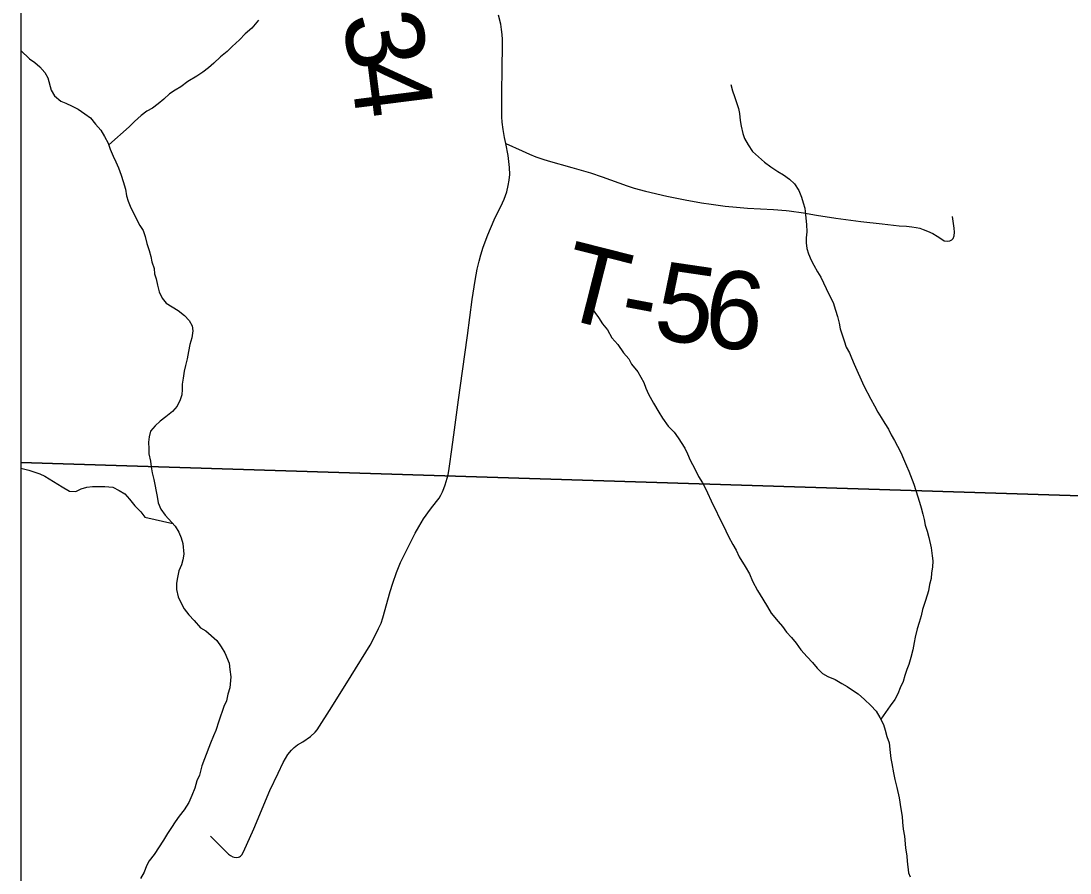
# Model space of a CAD drawing. Extents: x -3.3 to 34, y 0 to 56.8.
# Drawn here: x -3.304 to -2.54, y 30.466 to 31.087 of the extents above; entities that cross this region are included whole.
import ezdxf

# ---------------------------------------------------------------- set-up
doc = ezdxf.new("R2010")
doc.units = 0
for name, color, linetype in [('GM_X_Corporation', 7, 'Continuous'), ('GM_X_Township_Road', 7, 'Continuous'), ('GM_X_Township_Road_Text', 7, 'Continuous'), ('GT_Project_Soil_Layers', 7, 'Continuous'), ('SH_Data', 7, 'Continuous')]:
    doc.layers.add(name, color=color, linetype=linetype)

msp = doc.modelspace()

# ---------------------------------------------------------------- linework, layer by layer
at = {"layer": 'GM_X_Corporation'}
msp.add_lwpolyline([(-3.30393, 33.7379), (-3.30393, 28.07705), (1.56989, 28.07705), (1.59424, 28.73823), (1.64589, 29.81689), (1.65379, 30.0279), (1.68495, 30.79802), (1.68821, 30.98908), (1.68831, 30.9953), (1.68852, 31.00753), (1.69805, 31.56614), (1.74587, 32.36303)], dxfattribs=at)
for points in [[(-3.30393, 31.76721), (-3.30393, 30.76526), (-2.39277, 30.73672), (-2.35994, 31.74572)], [(-3.30393, 30.76526), (-3.30393, 29.75009), (-2.4143, 29.73246), (-2.39277, 30.73672)]]:
    msp.add_lwpolyline(points, close=True, dxfattribs=at)
at = {"layer": 'GM_X_Township_Road'}
for points in [[(-2.95067, 30.99779), (-2.95158, 31.00215), (-2.95268, 31.00803), (-2.95328, 31.01331), (-2.95355, 31.01711), (-2.95364, 31.03428), (-2.95329, 31.05262), (-2.95298, 31.06898), (-2.95306, 31.07358), (-2.95331, 31.0772), (-2.95372, 31.08082), (-2.95438, 31.08468), (-2.95595, 31.09131)], [(-3.16579, 30.49312), (-3.15398, 30.4811), (-3.1527, 30.47987), (-3.15124, 30.47886), (-3.14965, 30.47807), (-3.14851, 30.47774), (-3.14708, 30.47756), (-3.14545, 30.47785), (-3.1448, 30.47807), (-3.14398, 30.47849), (-3.14353, 30.479), (-3.14309, 30.47955), (-3.14179, 30.48165), (-3.13416, 30.49834), (-3.12262, 30.52641), (-3.11664, 30.53902), (-3.11294, 30.54667), (-3.10941, 30.55251), (-3.10694, 30.55579), (-3.10497, 30.55768), (-3.10242, 30.55949), (-3.09856, 30.56188), (-3.09289, 30.56574), (-3.08968, 30.56878), (-3.08812, 30.57051), (-3.07738, 30.58736), (-3.06339, 30.60989), (-3.04948, 30.63231), (-3.04628, 30.63824), (-3.0434, 30.64425), (-3.04159, 30.64827), (-3.04027, 30.65205), (-3.03493, 30.67132), (-3.03304, 30.67737), (-3.03041, 30.68509), (-3.02729, 30.69241), (-3.02063, 30.70598), (-3.01668, 30.71395), (-3.01405, 30.71855), (-3.0106, 30.72423), (-3.0055, 30.73137), (-3.00115, 30.7368), (-2.99929, 30.73925), (-2.99802, 30.74159), (-2.99686, 30.74399), (-2.99581, 30.74644), (-2.99487, 30.74893), (-2.99405, 30.75146), (-2.99334, 30.75402), (-2.99275, 30.75662), (-2.99228, 30.75924), (-2.9917, 30.76253), (-2.98997, 30.7747), (-2.98801, 30.78918), (-2.98508, 30.81087), (-2.98224, 30.83191), (-2.97866, 30.85786), (-2.97517, 30.88416), (-2.97297, 30.89792), (-2.97146, 30.90612), (-2.97016, 30.91197), (-2.96893, 30.91665), (-2.96721, 30.92217), (-2.96377, 30.93121), (-2.95912, 30.94206), (-2.95307, 30.95461), (-2.95184, 30.95725), (-2.95087, 30.95985), (-2.95005, 30.96256), (-2.94886, 30.96713), (-2.94823, 30.97107), (-2.9477, 30.97511), (-2.94788, 30.98031), (-2.94908, 30.98893), (-2.95067, 30.99779)], [(-2.95067, 30.99779), (-2.9387, 30.99239), (-2.93354, 30.98991), (-2.92885, 30.98806), (-2.9237, 30.98632), (-2.91993, 30.98521), (-2.90254, 30.98034), (-2.88891, 30.97638), (-2.88045, 30.97345), (-2.86214, 30.96681), (-2.85708, 30.96524), (-2.84898, 30.96303), (-2.83325, 30.95945), (-2.82009, 30.95669), (-2.80812, 30.95457), (-2.80104, 30.95346), (-2.79092, 30.95218), (-2.78267, 30.95134), (-2.77467, 30.95067), (-2.75554, 30.94977), (-2.74632, 30.94895)], [(-2.74632, 30.94895), (-2.74427, 30.94877), (-2.73387, 30.9473), (-2.72425, 30.94558), (-2.71013, 30.94343), (-2.69211, 30.94098), (-2.67636, 30.9392), (-2.66407, 30.93787), (-2.65875, 30.93746), (-2.65479, 30.937), (-2.65163, 30.93654), (-2.64912, 30.93598), (-2.64655, 30.93515), (-2.64331, 30.93395), (-2.63947, 30.93217), (-2.63641, 30.93031), (-2.63231, 30.9275), (-2.63118, 30.92693), (-2.62911, 30.92656), (-2.62724, 30.92686), (-2.6257, 30.92768), (-2.62469, 30.92857), (-2.62412, 30.93058), (-2.62384, 30.9332), (-2.62409, 30.936), (-2.62522, 30.94452)]]:
    msp.add_lwpolyline(points, dxfattribs=at)
at = {"layer": 'GT_Project_Soil_Layers'}
for points in [[(-3.13091, 31.08759), (-3.13576, 31.08183), (-3.14063, 31.07759), (-3.14474, 31.07335), (-3.14999, 31.06835), (-3.15373, 31.06488), (-3.15861, 31.06102), (-3.16348, 31.0564), (-3.16722, 31.05293), (-3.17135, 31.04984), (-3.17586, 31.04674), (-3.18225, 31.04286), (-3.18751, 31.03899), (-3.19165, 31.03666), (-3.19578, 31.03395), (-3.1999, 31.03009), (-3.20402, 31.02662), (-3.20815, 31.02353), (-3.21229, 31.0212), (-3.21642, 31.0181), (-3.22129, 31.01386), (-3.22503, 31.01002), (-3.23999, 30.9968)], [(-3.30393, 31.06552), (-3.29775, 31.05949), (-3.29392, 31.05689), (-3.29008, 31.05352), (-3.28661, 31.0494), (-3.28429, 31.04564), (-3.28189, 31.03656), (-3.27956, 31.03242), (-3.27496, 31.02869), (-3.27115, 31.02722), (-3.26657, 31.02501), (-3.26237, 31.02279), (-3.25739, 31.01944), (-3.25318, 31.01646), (-3.24971, 31.01195), (-3.24585, 31.00746), (-3.24314, 31.00294), (-3.24042, 30.99804), (-3.23884, 30.99351), (-3.23688, 30.9886), (-3.23493, 30.98446), (-3.23297, 30.97993), (-3.231, 30.97464), (-3.22942, 30.97011), (-3.22783, 30.96444), (-3.22701, 30.95952), (-3.22582, 30.95574), (-3.22386, 30.95083), (-3.21724, 30.93802), (-3.21491, 30.93426), (-3.21334, 30.93011), (-3.21213, 30.92481), (-3.21055, 30.9199), (-3.20935, 30.91536), (-3.20854, 30.91158), (-3.20696, 30.90667), (-3.20653, 30.90288), (-3.20534, 30.8991), (-3.20452, 30.89456), (-3.20331, 30.88964), (-3.20098, 30.88512), (-3.19827, 30.88136), (-3.19369, 30.87877), (-3.18948, 30.87617), (-3.18488, 30.87244), (-3.18142, 30.86869), (-3.17909, 30.86493), (-3.17866, 30.86114), (-3.17935, 30.8562), (-3.18081, 30.85124), (-3.18188, 30.8463), (-3.18294, 30.84097), (-3.18401, 30.83602), (-3.18509, 30.83183), (-3.18578, 30.82689), (-3.18648, 30.82233), (-3.18643, 30.81853), (-3.18676, 30.81473), (-3.18784, 30.81092), (-3.19006, 30.80634), (-3.19342, 30.8025), (-3.1983, 30.79864), (-3.20242, 30.79555), (-3.20617, 30.79208), (-3.20953, 30.78824), (-3.21061, 30.78405), (-3.21094, 30.78025), (-3.21087, 30.77532), (-3.21082, 30.77152), (-3.20961, 30.76623), (-3.20918, 30.76206), (-3.20836, 30.7579), (-3.20716, 30.75298), (-3.20472, 30.74049), (-3.2039, 30.73595), (-3.20194, 30.73142), (-3.19885, 30.72691), (-3.19154, 30.71904), (-3.18882, 30.71453), (-3.18725, 30.71037), (-3.18605, 30.70622), (-3.1852, 30.69864)], [(-2.78674, 31.04071), (-2.78554, 31.03617), (-2.78397, 31.03202), (-2.7812, 31.02333), (-2.78039, 31.01954), (-2.77994, 31.01462), (-2.77913, 31.01045), (-2.77792, 31.00515), (-2.77673, 31.00138), (-2.77401, 30.99686), (-2.77091, 30.99197), (-2.76209, 30.98412), (-2.75749, 30.98077), (-2.75252, 30.97742), (-2.74831, 30.97482), (-2.7441, 30.97185), (-2.74026, 30.96848), (-2.73716, 30.96359), (-2.7352, 30.95868), (-2.73401, 30.95453), (-2.73282, 30.95075), (-2.73238, 30.94582), (-2.73152, 30.93862), (-2.73145, 30.93331), (-2.73177, 30.92913), (-2.73172, 30.92534), (-2.73128, 30.92117), (-2.73009, 30.91739), (-2.72814, 30.91286), (-2.72619, 30.9091), (-2.72347, 30.9042), (-2.72115, 30.90044), (-2.71724, 30.89214), (-2.71451, 30.88649), (-2.71217, 30.88197), (-2.71058, 30.8763), (-2.709, 30.87176), (-2.7078, 30.86685), (-2.70699, 30.86268), (-2.70421, 30.854), (-2.70264, 30.84946), (-2.70031, 30.84532), (-2.69874, 30.84155), (-2.69678, 30.83702), (-2.68974, 30.82118), (-2.68468, 30.81138), (-2.68196, 30.80649), (-2.67963, 30.80196), (-2.6773, 30.7982), (-2.67458, 30.79368), (-2.67188, 30.78955), (-2.66992, 30.7854), (-2.66759, 30.78126), (-2.66526, 30.77712), (-2.66292, 30.7726), (-2.66097, 30.76807), (-2.65862, 30.76279), (-2.65705, 30.75901), (-2.65351, 30.74958), (-2.65194, 30.74504), (-2.64916, 30.73635), (-2.64797, 30.7322), (-2.64677, 30.72766), (-2.64596, 30.72388), (-2.64515, 30.71971), (-2.64357, 30.71518), (-2.64237, 30.71064), (-2.64075, 30.70308), (-2.63992, 30.6974), (-2.63949, 30.69361), (-2.63981, 30.68905), (-2.64051, 30.68486), (-2.64083, 30.68069), (-2.64191, 30.6765), (-2.64261, 30.67193), (-2.64479, 30.6647), (-2.64697, 30.65821), (-2.64805, 30.65364), (-2.6495, 30.64869), (-2.65095, 30.64412), (-2.65239, 30.63803), (-2.6531, 30.63422), (-2.65416, 30.6289), (-2.6556, 30.62318), (-2.65705, 30.61823), (-2.65852, 30.61442), (-2.65998, 30.61022), (-2.66105, 30.60565), (-2.66327, 30.60107), (-2.66511, 30.59687), (-2.66733, 30.59267), (-2.67068, 30.58807), (-2.67752, 30.57841)], [(-2.88884, 30.87916), (-2.88574, 30.87465), (-2.88303, 30.87089), (-2.88032, 30.86637), (-2.87647, 30.86187), (-2.87336, 30.85622), (-2.86912, 30.85135), (-2.86487, 30.84533), (-2.86102, 30.84083), (-2.85907, 30.83707), (-2.85444, 30.83144), (-2.85017, 30.82353), (-2.84859, 30.81937), (-2.84664, 30.81523), (-2.84314, 30.80844), (-2.83926, 30.80205), (-2.83655, 30.79753), (-2.8323, 30.7919), (-2.82806, 30.7874), (-2.82498, 30.78327), (-2.82033, 30.77574), (-2.81837, 30.7716), (-2.81642, 30.76707), (-2.81292, 30.76067), (-2.81019, 30.75501), (-2.80747, 30.7505), (-2.80514, 30.74635), (-2.79967, 30.73428), (-2.79772, 30.73052), (-2.79538, 30.72562), (-2.79227, 30.71959), (-2.78836, 30.71129), (-2.78526, 30.70564), (-2.78292, 30.7015), (-2.78058, 30.6966), (-2.77631, 30.68945), (-2.77321, 30.68418), (-2.77087, 30.6789), (-2.76736, 30.67212), (-2.76348, 30.66572), (-2.75999, 30.66008), (-2.75728, 30.65556), (-2.75227, 30.64956), (-2.74919, 30.64581), (-2.74609, 30.64167), (-2.74263, 30.63792), (-2.73916, 30.6338), (-2.73569, 30.62891), (-2.73106, 30.62367), (-2.72722, 30.61954), (-2.72375, 30.61542), (-2.71991, 30.61168), (-2.71609, 30.60945), (-2.71075, 30.60725), (-2.70578, 30.60428), (-2.70196, 30.60206), (-2.69813, 30.59945), (-2.69392, 30.59685), (-2.68932, 30.59274), (-2.68471, 30.58825), (-2.68086, 30.58413), (-2.67814, 30.57962), (-2.67542, 30.57434), (-2.67423, 30.57018), (-2.67303, 30.56565), (-2.67145, 30.56111), (-2.67059, 30.55392), (-2.67016, 30.54975), (-2.66935, 30.54596), (-2.66812, 30.53915), (-2.6673, 30.53423), (-2.6657, 30.52856), (-2.66408, 30.52099), (-2.66284, 30.51304), (-2.662, 30.50736), (-2.66157, 30.50319), (-2.66112, 30.49827), (-2.66029, 30.49296), (-2.65942, 30.48463), (-2.65858, 30.47857), (-2.65815, 30.47478), (-2.65728, 30.46644), (-2.6561, 30.46342)], [(-3.30393, 30.76113), (-3.29825, 30.7597), (-3.29445, 30.75861), (-3.29026, 30.75715), (-3.28644, 30.75531), (-3.27382, 30.74751), (-3.26847, 30.74455), (-3.26392, 30.74423), (-3.26015, 30.74618), (-3.256, 30.74738), (-3.25183, 30.74782), (-3.24274, 30.74794), (-3.23704, 30.74726), (-3.23246, 30.74504), (-3.22825, 30.74245), (-3.22479, 30.7387), (-3.22093, 30.73382), (-3.2167, 30.72932), (-3.21362, 30.72557), (-3.19329, 30.72092)], [(-3.1852, 30.69864), (-3.1859, 30.69446), (-3.18698, 30.69065), (-3.18882, 30.68645), (-3.18989, 30.6815), (-3.19059, 30.67732), (-3.19053, 30.67276), (-3.18932, 30.66747), (-3.18776, 30.6637), (-3.18504, 30.6588), (-3.18156, 30.65429), (-3.17772, 30.65017), (-3.17309, 30.64492), (-3.16927, 30.6427), (-3.16122, 30.6356), (-3.15812, 30.63109), (-3.15541, 30.62657), (-3.15227, 30.61903), (-3.15183, 30.61448), (-3.151, 30.60918), (-3.15165, 30.6012), (-3.15311, 30.59663), (-3.15418, 30.59168), (-3.15602, 30.58748), (-3.15967, 30.5768), (-3.16185, 30.56994), (-3.16369, 30.56613), (-3.16589, 30.56078), (-3.17029, 30.54934), (-3.17212, 30.54438), (-3.17392, 30.53753), (-3.17576, 30.53333), (-3.17721, 30.528), (-3.17941, 30.52265), (-3.18162, 30.51769), (-3.18496, 30.51233), (-3.18869, 30.50773), (-3.19167, 30.50351), (-3.19426, 30.4993), (-3.19724, 30.49509), (-3.20021, 30.49011), (-3.20689, 30.47978), (-3.21062, 30.47517), (-3.21247, 30.47135), (-3.2143, 30.46678), (-3.21689, 30.46219)]]:
    msp.add_lwpolyline(points, dxfattribs=at)
at = {"layer": 'SH_Data'}
msp.add_line((-3.30393, 34.87705), (-3.30393, 28.07705), dxfattribs=at)

# ---------------------------------------------------------------- texts
at = {"layer": 'GM_X_Township_Road_Text'}
for s, rotation, p in [('3', 278.96141, (-3.06982, 31.0902)), ('4', 277.21603, (-3.06443, 31.05608)), ('T', 345.79642, (-2.91479, 30.87203)), ('5', 351.63046, (-2.84447, 30.85607)), ('6', 353.2907, (-2.80806, 30.85074)), ('-', 349.37783, (-2.86981, 30.86077))]:
    msp.add_text(s, height=0.05682, rotation=rotation, dxfattribs=at).set_placement(p)

doc.saveas('drawing.dxf')
